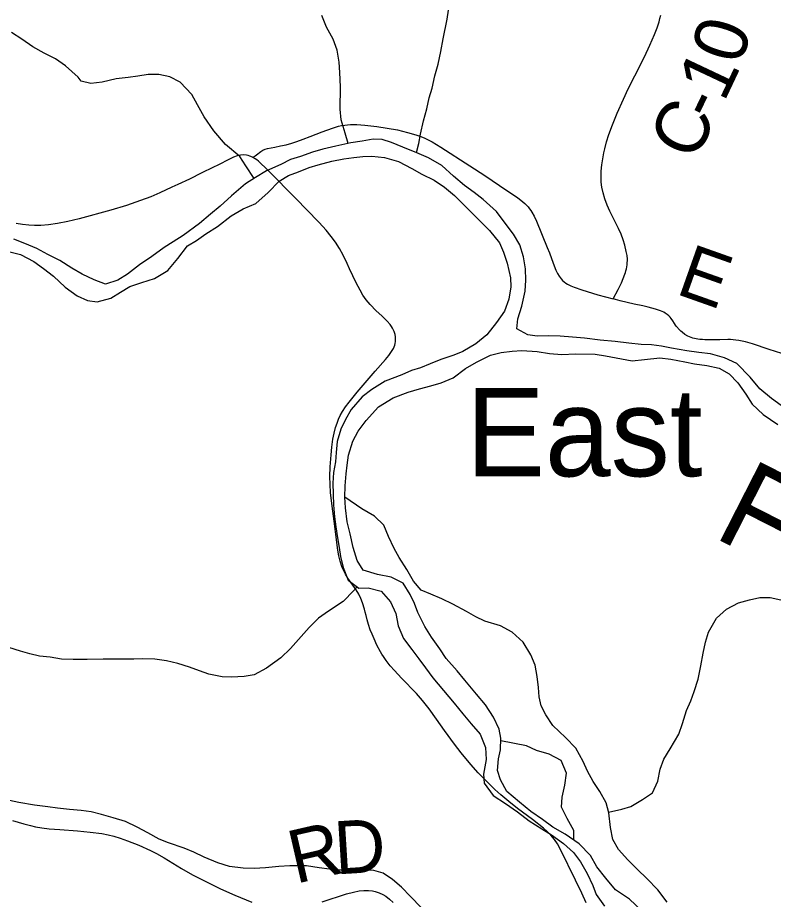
# Model space of a CAD drawing. Extents: x 1451455 to 1749751, y 218250 to 574981.
# Drawn here: x 1620554 to 1624828, y 285699 to 290686 of the extents above; entities that cross this region are included whole.
import ezdxf

# ---------------------------------------------------------------- set-up
doc = ezdxf.new("R2010")
doc.units = 0
for name, color, linetype in [('GM_X_County_Road', 7, 'Continuous'), ('GM_X_County_Road_Text', 7, 'Continuous'), ('GM_X_Minor_River', 7, 'Continuous'), ('GM_X_Minor_River_Text', 7, 'Continuous'), ('GM_X_State_Route', 7, 'Continuous'), ('GM_X_Township_Road', 7, 'Continuous'), ('GM_X_Township_Road_Text', 7, 'Continuous')]:
    doc.layers.add(name, color=color, linetype=linetype)

msp = doc.modelspace()

# ---------------------------------------------------------------- linework, layer by layer
at = {"layer": 'GM_X_County_Road'}
for points in [[(1623920.9, 289095.4), (1623950.2, 289148.7), (1623967.8, 289185.7), (1623978.2, 289210.2), (1623987.7, 289234.6), (1623990.6, 289243.5), (1623993.5, 289253.7), (1623996.4, 289264.6), (1623998.7, 289276.3), (1624000.3, 289287.4), (1624001.5, 289299.8), (1624002.3, 289309.5), (1624002, 289319.9), (1624000.1, 289339.9), (1623995.9, 289362.7), (1623987.3, 289398), (1623977.7, 289429.5), (1623966.1, 289460.3), (1623951.3, 289493.3), (1623924.7, 289545.5), (1623902.2, 289591.9), (1623888.4, 289624.6), (1623875.2, 289661.2), (1623865.2, 289695.4), (1623858.3, 289727), (1623854.6, 289755.8), (1623853.2, 289784.9), (1623854, 289817.3), (1623857.4, 289852.9), (1623860.7, 289875.9), (1623864.4, 289898), (1623868.5, 289920.2), (1623873.6, 289942.7), (1623884.2, 289983.8), (1623897, 290024.2), (1623917.7, 290079.2), (1623945, 290145.8), (1623979.3, 290223.7), (1624007.3, 290282.9), (1624044, 290356.1), (1624098.3, 290464.7), (1624129.4, 290530), (1624155.9, 290590.1), (1624170.3, 290627), (1624181.3, 290661.7), (1624186.3, 290680.6), (1624190.4, 290700.2)], [(1622208, 290012.7), (1622276.4, 290039.1), (1622334.6, 290060.9), (1622351.2, 290066.1), (1622368.7, 290071.1), (1622385.7, 290074.9), (1622403.5, 290078), (1622419.6, 290079.8), (1622435.7, 290080.9), (1622452.8, 290081.4), (1622471.4, 290080.9), (1622516.9, 290077.7), (1622585.1, 290069.8), (1622643.3, 290061.1), (1622701.2, 290050.2), (1622758.3, 290036.6), (1622792.9, 290026.9), (1622811.4, 290021.5), (1622834.4, 290013.3), (1622856.7, 290003.3), (1622897.1, 289982.3), (1622947.7, 289952.5), (1623110.6, 289848.1), (1623195.4, 289792.1), (1623320.7, 289708.1), (1623380.5, 289668), (1623411.4, 289644.3), (1623422.8, 289634.4), (1623432.4, 289624.5), (1623440.7, 289615.1), (1623448.8, 289604.8), (1623455.7, 289594.6), (1623461.4, 289586.2), (1623474, 289563.6), (1623487.6, 289534.1), (1623548.1, 289385.4), (1623560.8, 289355.2), (1623582.4, 289297), (1623598, 289257.3), (1623606.9, 289238.7), (1623615.6, 289224.3), (1623627.8, 289208.1), (1623635.5, 289199.7), (1623644.6, 289191.4), (1623654, 289184.7), (1623663.9, 289178), (1623681.5, 289168.6), (1623700.2, 289160.9), (1623744.1, 289146.1), (1623835.3, 289118.5), (1623878.2, 289106.8), (1623920.9, 289095.4)], [(1621883.8, 289895.4), (1621903.9, 289910.4), (1621928.8, 289929), (1621940.3, 289935.8), (1621952.7, 289940.8), (1621967.2, 289944.9), (1622007.5, 289953.3), (1622039.6, 289959.7), (1622071.7, 289967.1), (1622103.5, 289975.8), (1622131.9, 289984.7), (1622169.2, 289997.7), (1622208, 290012.7)], [(1620525.1, 286144.5), (1620588.2, 286126.4), (1620626.2, 286116.2), (1620654.9, 286109.6), (1620690.4, 286103.4), (1620732.7, 286098.4), (1620791.5, 286094.1), (1620893, 286086.4), (1620964.8, 286079.3), (1621029.9, 286070.7), (1621065.4, 286064.4), (1621097.8, 286056.4), (1621134.2, 286045.2), (1621175, 286029.5), (1621238.7, 286004.4), (1621305.3, 285974.9), (1621339.8, 285957.4), (1621382.6, 285933.3), (1621480.7, 285873.7), (1621543.2, 285837.7), (1621610.3, 285803.5), (1621701.3, 285758.8), (1621781.5, 285722.5), (1621877.9, 285681.8)], [(1622275.7, 285684.9), (1622412.9, 285729.6), (1622453.7, 285740), (1622486, 285746.1), (1622511.9, 285748.6), (1622538, 285748.7), (1622560.6, 285746.1), (1622576.4, 285742.7), (1622598.1, 285735.8), (1622618.6, 285726.1), (1622635.2, 285716.1), (1622656.1, 285700.6), (1622677.9, 285681.1)]]:
    msp.add_lwpolyline(points, dxfattribs=at)
at = {"layer": 'GM_X_Minor_River'}
for points in [[(1622422.5, 289973.8), (1622406.2, 290031.6), (1622383.1, 290108), (1622377.7, 290168.1), (1622379.2, 290294.2), (1622376.1, 290374.4), (1622372.7, 290434.5), (1622361.5, 290500.7), (1622338.2, 290563), (1622300.9, 290631.5), (1622273.6, 290697.9)], [(1622808.9, 289922), (1622821.9, 289973), (1622832.5, 290026.9), (1622849.4, 290102.8), (1622868.2, 290170.7), (1622880.9, 290232.6), (1622897.5, 290286.5), (1622912.3, 290356.5), (1622931.1, 290422.3), (1622947.9, 290494.2), (1622960.7, 290566.2), (1622982, 290676.1), (1622990.6, 290728.1)], [(1621891.8, 289776.3), (1621843.7, 289847.5), (1621810.2, 289900), (1621728.9, 289969), (1621663.8, 290045.8), (1621608.6, 290124.5), (1621571.3, 290193), (1621538, 290251.4), (1621472.7, 290320.2), (1621415, 290350.9), (1621353.1, 290363.6), (1621291, 290364.3), (1621232.9, 290354.9), (1621178.7, 290347.5), (1621110.6, 290340.2), (1621032.3, 290321.1), (1620968.2, 290313.8), (1620912.3, 290326.4), (1620896.5, 290348.6), (1620825.2, 290413.5), (1620767.6, 290452.2), (1620703.9, 290484.9), (1620640.2, 290519.6), (1620576.7, 290564.4), (1620519.1, 290601.1)], [(1624892.8, 288476.1), (1624817.3, 288531), (1624751.9, 288585.8), (1624696.6, 288652.5), (1624621.4, 288729.5), (1624551.7, 288762.3), (1624471.9, 288783.2), (1624405.9, 288791.9), (1624338, 288800.7), (1624252.1, 288815.6), (1624194.2, 288828.3), (1624138.2, 288834.9), (1624080.2, 288837.6), (1624010.2, 288844.3), (1623932.2, 288853.2), (1623848.2, 288862.2), (1623760.3, 288873.1), (1623692.3, 288877.9), (1623622.3, 288884.7), (1623558.3, 288885.4), (1623492.2, 288884.1), (1623438.2, 288890.7), (1623376.6, 288925.5), (1623383.2, 288981.5), (1623406, 289053.3), (1623423, 289139.2), (1623427.7, 289201.3), (1623426.4, 289265.4), (1623415.2, 289333.6), (1623393.9, 289399.9), (1623358.6, 289460.4), (1623311.2, 289523), (1623262, 289589.6), (1623186.6, 289656.5), (1623135.1, 289697.1), (1623081.5, 289735.8), (1623018, 289788.5), (1622952.6, 289849.3), (1622877, 289892.2), (1622811.3, 289921), (1622731.6, 289953.9), (1622667.8, 289978.6), (1622616, 289997.2), (1622564, 289997.8), (1622501.8, 289986.5), (1622437.6, 289977.2), (1622353.3, 289958.1), (1622279.1, 289940.9), (1622220.9, 289925.5), (1622152.5, 289900.2), (1622096.3, 289882.8), (1622041.9, 289855.4), (1621961.4, 289818.2), (1621899, 289780.8), (1621842.5, 289745.4), (1621763.7, 289678.2), (1621699, 289618.8), (1621644.4, 289573.4), (1621581.8, 289522), (1621488.9, 289452.9), (1621432.5, 289417.5), (1621382.1, 289386), (1621313.4, 289334.7)], [(1620948.3, 289086.3), (1621004.3, 289077.7), (1621080.6, 289098.9), (1621135, 289132.4), (1621187.4, 289165.8), (1621255.7, 289187.1), (1621328.1, 289210.3), (1621402.6, 289255.6), (1621459.4, 289323.1), (1621514.3, 289394.6), (1621564.7, 289426), (1621617.2, 289463.5), (1621683.7, 289504.8), (1621760.4, 289564.1), (1621828.9, 289603.4), (1621901.3, 289634.6), (1621970.1, 289696), (1622032.9, 289761.3), (1622085.3, 289792.8), (1622141.5, 289814.2), (1622201.9, 289837.6), (1622254.1, 289853), (1622330.4, 289874.2), (1622398.6, 289887.5), (1622454.7, 289894.9), (1622506.8, 289900.3), (1622556.9, 289901.8), (1622628.9, 289895), (1622706.7, 289872.1), (1622782.3, 289833.2), (1622840, 289800.5), (1622909.6, 289765.7), (1622967.2, 289727), (1623024.8, 289680.3), (1623096, 289607.5), (1623171.2, 289532.5), (1623222.7, 289481.9), (1623278, 289411.2), (1623301.4, 289358.9), (1623322.7, 289296.5), (1623341.8, 289214.2), (1623343.2, 289162.1), (1623332.4, 289094.2), (1623307.6, 289026.3), (1623260.9, 288960.8), (1623208, 288891.3), (1623145.4, 288839.9), (1623070.8, 288796.6), (1623020.6, 288777.2), (1622946.2, 288752), (1622885.9, 288726.6), (1622831.6, 288705.1), (1622781.4, 288689.7), (1622727.1, 288666.2), (1622632.6, 288629.2), (1622556, 288582), (1622501.5, 288540.5), (1622440.6, 288469.1), (1622408, 288413.4), (1622381.3, 288357.6), (1622360.5, 288287.8), (1622355.8, 288225.7), (1622351.2, 288173.7), (1622340.6, 288113.7), (1622335.9, 288051.7), (1622337.2, 287989.6), (1622340.5, 287929.5), (1622345.7, 287861.3), (1622353.1, 287805.2), (1622362.4, 287743), (1622371.8, 287688.8), (1622379.2, 287638.6), (1622394.6, 287576.4), (1622423.8, 287504), (1622483.3, 287459.2), (1622535.4, 287460.7), (1622609.2, 287441.8), (1622662.6, 287381.2), (1622691.9, 287314.8), (1622705.1, 287246.5), (1622736.3, 287174.1), (1622783.7, 287111.5), (1622823.1, 287059), (1622860.6, 287008.5), (1622901.9, 286951.9), (1622961.2, 286879.2), (1623022.4, 286808.4), (1623071.8, 286747.8), (1623119.2, 286691.2), (1623168.6, 286632.6), (1623199.8, 286558.1), (1623203, 286490), (1623188.1, 286406), (1623191.5, 286355.9), (1623242.7, 286285.3), (1623312.3, 286240.4), (1623379.8, 286193.6), (1623447.3, 286142.8), (1623518.9, 286098), (1623572.5, 286063.3), (1623640, 286014.5)], [(1621313.4, 289334.7), (1621242.8, 289287.4), (1621174.2, 289234.1), (1621119.8, 289200.6), (1621051.5, 289177.3), (1620985.7, 289202.1), (1620918, 289234.9), (1620860.3, 289269.5), (1620792.8, 289312.4), (1620725.1, 289345.1), (1620661.4, 289379.9), (1620593.7, 289408.7), (1620531.9, 289433.4)], [(1620509.1, 289361.5), (1620569, 289346.8), (1620644.6, 289306), (1620700.2, 289267.3), (1620755.7, 289222.6), (1620823.1, 289161.8), (1620890.6, 289113), (1620948.3, 289086.3)], [(1624080.2, 285637.1), (1624014.8, 285699.9), (1623935.3, 285752.9), (1623880, 285817.6), (1623828.7, 285882.2), (1623793.4, 285946.7), (1623730.1, 286013.5), (1623650.6, 286066.5), (1623581, 286107.3), (1623521.5, 286150), (1623455.9, 286194.8), (1623392.4, 286247.6), (1623321.1, 286308.4), (1623283.8, 286374.9), (1623268.4, 286427.2), (1623273.1, 286493.2), (1623283.7, 286545.2), (1623286.4, 286611.2), (1623277, 286661.4), (1623245.7, 286729.8), (1623200.5, 286798.5), (1623149.1, 286859.1), (1623081.9, 286938), (1623038.5, 286990.5), (1622977.2, 287061.3), (1622941.8, 287115.7), (1622894.5, 287182.3), (1622857.2, 287242.8), (1622816, 287321.4), (1622798.6, 287371.7), (1622773.1, 287422), (1622733.8, 287486.5), (1622666.2, 287521.3), (1622588.3, 287536.2), (1622508.5, 287561.1), (1622473.1, 287615.6), (1622451.9, 287687.9), (1622434.7, 287766.2), (1622417.5, 287834.5), (1622408.3, 287912.7), (1622405, 287972.8), (1622405.7, 288036.9), (1622412.5, 288104.9), (1622417.1, 288154.9), (1622425.7, 288210.9), (1622448.6, 288290.8), (1622479.3, 288346.5), (1622524, 288406.1), (1622594.9, 288483.5), (1622677.6, 288534.6), (1622762, 288567.7), (1622826.3, 288587), (1622890.5, 288602.4), (1622948.8, 288619.8), (1623017.1, 288649), (1623085.8, 288700.3), (1623148.2, 288737.7), (1623228.8, 288776.9), (1623289, 288792.2), (1623351.1, 288799.6), (1623405.2, 288803), (1623491.2, 288798), (1623561.1, 288785.2), (1623631.1, 288780.5)], [(1623631.1, 288780.5), (1623709.2, 288783.6), (1623819.3, 288782.4), (1623877.3, 288773.7), (1624029.1, 288744), (1624099.2, 288751.2), (1624185.4, 288762.3), (1624247.4, 288753.6), (1624327.3, 288738.7), (1624381.2, 288728.1), (1624451.1, 288717.3), (1624521, 288702.5), (1624576.7, 288671.9), (1624626.2, 288619.2), (1624671.5, 288556.7), (1624706.9, 288500.2), (1624770.3, 288441.4), (1624853.7, 288384.4)], [(1624226.8, 285683.6), (1624173.5, 285752.3), (1624112.2, 285817), (1624058.7, 285867.7), (1624005.3, 285922.4), (1623951.9, 285981), (1623920.5, 286037.5), (1623907.3, 286105.7), (1623896.2, 286187.9), (1623882.8, 286244.2), (1623845.5, 286308.7), (1623808.1, 286365.2), (1623776.7, 286423.6), (1623751.3, 286478), (1623710.2, 286554.5), (1623652.8, 286613.2), (1623579.5, 286682.1), (1623540.1, 286742.6), (1623514.7, 286793), (1623503.2, 286843.2), (1623499.8, 286897.3), (1623492.5, 286959.5), (1623481.2, 287023.7), (1623455.9, 287082), (1623412.6, 287152.6), (1623351.2, 287209.4), (1623283.6, 287246.2), (1623195.8, 287271.2), (1623144, 287295.8), (1623092.3, 287326.4), (1623014.7, 287367.3), (1622953, 287398), (1622891.3, 287424.7), (1622835.5, 287447.4), (1622792, 287497.9), (1622754.7, 287564.4), (1622711.4, 287633), (1622684, 287683.4), (1622650.7, 287751.8), (1622625.4, 287814.2), (1622572, 287866.8), (1622500.4, 287907.7), (1622405, 287973.7)], [(1622473.8, 287466.3), (1622455.1, 287445.5), (1622394.4, 287384.1), (1622311.7, 287329), (1622255.2, 287289.5), (1622202.6, 287236), (1622158, 287184.4), (1622097.1, 287117), (1622042.5, 287065.5), (1621961.8, 287006.3), (1621891.3, 286969), (1621835.2, 286959.6), (1621763, 286954.4), (1621711, 286957), (1621635.1, 286971.8), (1621581.3, 286990.5), (1621525.5, 287011.1), (1621459.7, 287031.9), (1621395.8, 287048.6), (1621329.8, 287057.3), (1621261.8, 287058.1), (1621211.7, 287056.6), (1621093.7, 287057.9), (1621037.6, 287056.5), (1620947.5, 287055.5), (1620867.4, 287054.4), (1620801.4, 287057.1), (1620737.5, 287067.8), (1620677.5, 287074.5), (1620623.6, 287087.1), (1620569.7, 287101.7), (1620503.9, 287122.4)], [(1623895.2, 286192.2), (1623970.5, 286209.1), (1624020.7, 286224.6), (1624087.2, 286264), (1624143.7, 286301.4), (1624174.4, 286367.1), (1624187.2, 286435.1), (1624207.9, 286490.9), (1624244.6, 286550.6), (1624293.5, 286632.2), (1624314.2, 286694), (1624337.1, 286765.9), (1624361.7, 286821.7), (1624380.3, 286873.6), (1624403.1, 286943.4), (1624418, 287019.4), (1624430.8, 287091.3), (1624443.5, 287153.3), (1624460.1, 287209.2), (1624505.1, 287288.8), (1624561.7, 287340.2), (1624630.2, 287375.5), (1624692.4, 287392.8), (1624750.6, 287406.2), (1624808.6, 287405.6), (1624886.5, 287388.7)], [(1623699.4, 286033.9), (1623698.9, 286088), (1623661.6, 286156.5), (1623630.3, 286220.9), (1623633, 286277), (1623647.7, 286344.9), (1623658.5, 286412.9), (1623627.3, 286483.3), (1623559.6, 286520.1), (1623487.8, 286540.9), (1623432.1, 286567.6), (1623285.8, 286595.7)], [(1622835.3, 285652.8), (1622776, 285715.6), (1622724.5, 285768.2), (1622672.9, 285810.8), (1622621.3, 285847.4), (1622567.4, 285862), (1622499.4, 285864.8), (1622431.3, 285863.5), (1622379.3, 285864.1), (1622317.3, 285868.8), (1622259.4, 285877.5), (1622187.4, 285888.2), (1622093.3, 285887.3), (1622031.2, 285884), (1621955.1, 285876.8), (1621891, 285873.5), (1621829, 285874.1), (1621751, 285885), (1621685.2, 285905.8), (1621609.5, 285936.6), (1621549.7, 285965.3), (1621496, 285988), (1621406.2, 286019), (1621354.4, 286039.6), (1621290.8, 286074.3), (1621229.1, 286107), (1621163.4, 286139.8), (1621093.6, 286160.6), (1621027.7, 286179.4), (1620969.8, 286194), (1620913.9, 286200.6), (1620847.9, 286207.4), (1620779.9, 286214.1), (1620724, 286222.7), (1620650, 286231.6), (1620560.1, 286246.6), (1620482.2, 286263.4)], [(1623640, 286014.5), (1623697.5, 285963.8), (1623736.9, 285911.3), (1623774.2, 285844.8), (1623807.5, 285776.3), (1623824.9, 285726.1), (1623872.2, 285659.5)]]:
    msp.add_lwpolyline(points, dxfattribs=at)
at = {"layer": 'GM_X_State_Route'}
for points in [[(1622130.6, 289658.2), (1621968.8, 289822.8), (1621916.1, 289873.5), (1621906.9, 289880.8), (1621897.6, 289887.7), (1621883.8, 289895.4), (1621882.4, 289896.2), (1621867.2, 289902.7), (1621857.2, 289905.9), (1621848.4, 289907.7), (1621829.8, 289909.4), (1621813.7, 289908.1), (1621805, 289906.5), (1621795.3, 289904), (1621774.7, 289895.6), (1621748.3, 289883.3), (1621689.1, 289853.9), (1621657.2, 289837.6), (1621595.4, 289807.3), (1621524.9, 289772.5), (1621459.7, 289741.4), (1621426.2, 289726.1)], [(1621426.2, 289726.1), (1621358.4, 289695.1), (1621306.8, 289673), (1621249.3, 289651.1), (1621168.6, 289624), (1621081, 289597), (1620901.1, 289546.9), (1620837.3, 289532.2), (1620779.5, 289521), (1620727.8, 289513.5), (1620685.7, 289510.1), (1620649.9, 289509.8), (1620617.5, 289511.6), (1620582.1, 289515.8), (1620546, 289521.7)], [(1623769.4, 285679.6), (1623744.6, 285733.3), (1623709.2, 285807.4), (1623624.3, 285981.5), (1623606.3, 286013.2), (1623589.2, 286037.8), (1623570, 286060.8), (1623549.1, 286082.2), (1623526.7, 286101.9), (1623464.5, 286150.5), (1623380.3, 286213.2), (1623331.3, 286251.5), (1623286.1, 286289.2), (1623251.9, 286319.5), (1623200.7, 286370.1), (1623157.7, 286414.9), (1623116.6, 286461.6), (1623061.9, 286526.9), (1623023.5, 286575.7), (1622968.1, 286652.8), (1622923.4, 286717.7), (1622881, 286776.3), (1622844.1, 286822.7), (1622809.5, 286862.4), (1622724.9, 286949.7), (1622684.4, 286992.4), (1622661, 287019.4), (1622637.5, 287050.5), (1622622.6, 287072.9), (1622614.2, 287085.6), (1622605.8, 287099.4), (1622585.9, 287136.3), (1622569.5, 287171.5), (1622558.6, 287198), (1622548.3, 287223.7), (1622538.5, 287252.6), (1622531.2, 287280.4), (1622524.4, 287304.9), (1622519.5, 287323.3), (1622515.3, 287339), (1622504.1, 287376.6), (1622494.9, 287400.8), (1622483.3, 287424.1), (1622468, 287449.1), (1622421.4, 287515.3), (1622407.9, 287537), (1622397.6, 287556.8), (1622387.7, 287580.5), (1622377.7, 287611.1), (1622369.7, 287642.4), (1622363.8, 287674.4), (1622353.6, 287762.1), (1622343.7, 287837.1), (1622332.6, 287921.6), (1622323.6, 287999.5), (1622320.4, 288044.8), (1622318.9, 288090.8), (1622320.6, 288145.5), (1622325.9, 288213.4), (1622330.2, 288255.8), (1622337, 288302.2), (1622343.2, 288335.2), (1622352.2, 288368.3), (1622360.1, 288392.5), (1622368.8, 288413.7), (1622378.5, 288434.5), (1622391, 288457.1), (1622408.8, 288484.3), (1622428, 288510.5), (1622473.1, 288566.6), (1622575.5, 288686.1), (1622634.4, 288751.9), (1622653.3, 288775), (1622668.8, 288796.8), (1622678.6, 288814.5), (1622686.4, 288833.4), (1622688.8, 288842.9), (1622690.8, 288853.2), (1622691.5, 288863.7), (1622690.7, 288880.8), (1622688.3, 288894.2), (1622683.2, 288910.5), (1622674.4, 288928.9), (1622668.2, 288938.9), (1622660.5, 288949.8), (1622643.5, 288968.8), (1622612.5, 288998.1), (1622581.6, 289027.1), (1622547.9, 289062.4), (1622525.2, 289090), (1622506.5, 289116.4), (1622489.9, 289144.4), (1622468.7, 289184.9), (1622431.3, 289265), (1622417.5, 289294.8), (1622394.4, 289342.1), (1622373.9, 289379.8), (1622351, 289416.2), (1622327.5, 289448.1), (1622298, 289483.7), (1622258.1, 289527.5), (1622187.2, 289600.6), (1622130.6, 289658.2)]]:
    msp.add_lwpolyline(points, dxfattribs=at)
at = {"layer": 'GM_X_Township_Road'}
msp.add_lwpolyline([(1624874.7, 288785.6), (1624804.4, 288808.7), (1624708.9, 288839.9), (1624670.1, 288851.2), (1624631.8, 288859.4), (1624615.2, 288862.2), (1624599.5, 288864.1), (1624584.3, 288865.1), (1624570.1, 288865.4), (1624524.3, 288864), (1624468.5, 288863), (1624439.1, 288864), (1624426.2, 288864.8), (1624412.4, 288866.1), (1624400.4, 288867.6), (1624391.6, 288869), (1624381.1, 288871.2), (1624372, 288873.2), (1624362.2, 288876.7), (1624344, 288884.3), (1624326.9, 288894), (1624311.2, 288905.7), (1624303.7, 288912), (1624296.8, 288919.2), (1624279.6, 288939.1), (1624273.4, 288947.1), (1624268.2, 288955), (1624259.7, 288970.1), (1624250.3, 288984.6), (1624244.8, 288991.4), (1624236, 288999.8), (1624226.2, 289007.3), (1624216.5, 289013.8), (1624207.3, 289019.3), (1624189.5, 289027.6), (1624161.6, 289037.3), (1624120.4, 289048.4), (1624088.6, 289055.9), (1624040.7, 289065.7), (1624000.6, 289073.9), (1623960.7, 289083.8), (1623920.9, 289095.4)], dxfattribs=at)

# ---------------------------------------------------------------- texts
at = {"layer": 'GM_X_County_Road_Text'}
for s, rotation, p in [('0', 72.6938, (1624643, 290411.5)), ('1', 64.7273, (1624547.6, 290202)), ('-', 64.388, (1624493.5, 290089.1)), ('C', 63.4568, (1624381, 289863.9)), ('R', 12.9712, (1622125.4, 285785.9)), ('D', 3.5722, (1622352.6, 285839.3))]:
    msp.add_text(s, height=300, rotation=rotation, dxfattribs=at).set_placement(p)
at = {"layer": 'GM_X_Minor_River_Text'}
for s, height, rotation, p in [('East', 500, 359.9962, (1623089.7, 288091.6)), ('Fork', 500.04, 332.9948, (1624478.3, 287751.9))]:
    msp.add_text(s, height=height, rotation=rotation, dxfattribs=at).set_placement(p)
at = {"layer": 'GM_X_Township_Road_Text'}
msp.add_text('E', height=300, rotation=340.4975, dxfattribs=at).set_placement((1624268.3, 289126.2))

doc.saveas('drawing.dxf')
